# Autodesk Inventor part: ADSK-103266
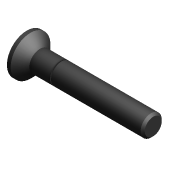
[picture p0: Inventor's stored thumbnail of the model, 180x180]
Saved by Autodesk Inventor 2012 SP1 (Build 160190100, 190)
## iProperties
Created: 2000-11
Part Number: ADSK-103266
Description: Hexagon Socket Countersunk Head Screw
Document SubType Name: Modeling
Standard: ISO 10642 - M5 x  30
Designer: donna
Density: 1 g/cm^3
Material: Default
Control State: 0
Master: False
Checked Out: False
Shininess: 0.0
Density: 0.0
Volumn: 0.0
Area: 0.0
PropertySet Name: Model Information
Author: donna
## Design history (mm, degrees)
node "Base1"
body "Solid1"
